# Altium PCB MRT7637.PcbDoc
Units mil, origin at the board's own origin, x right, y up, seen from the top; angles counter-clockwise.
Board outline 6000 x 4000 mil, 2 copper layers (Top Layer, Bottom Layer); 1 components, 0 nets, 5 pads, 0 vias.
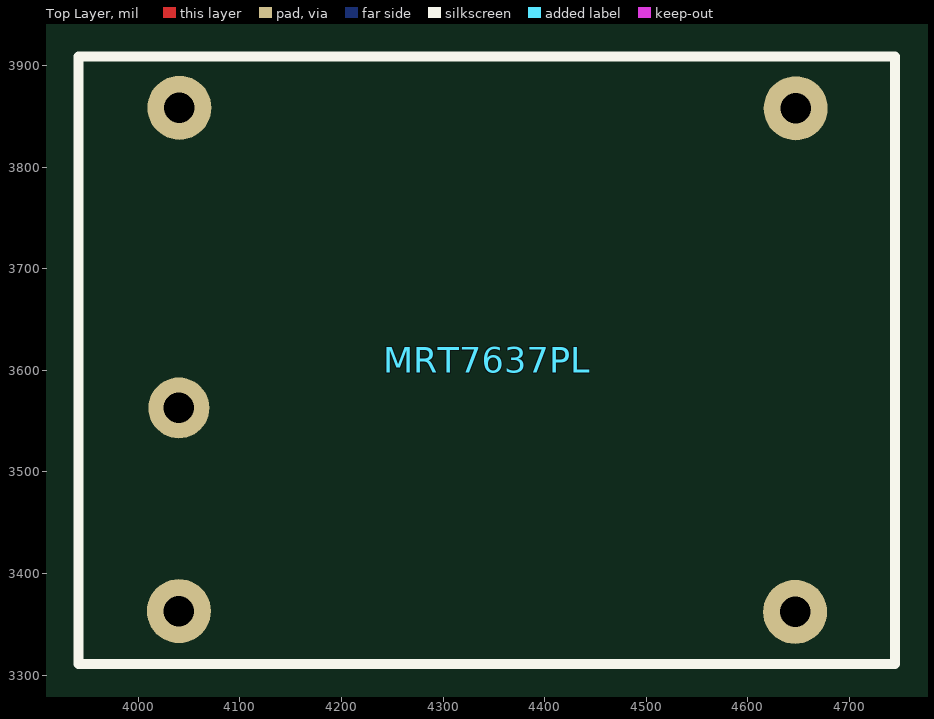
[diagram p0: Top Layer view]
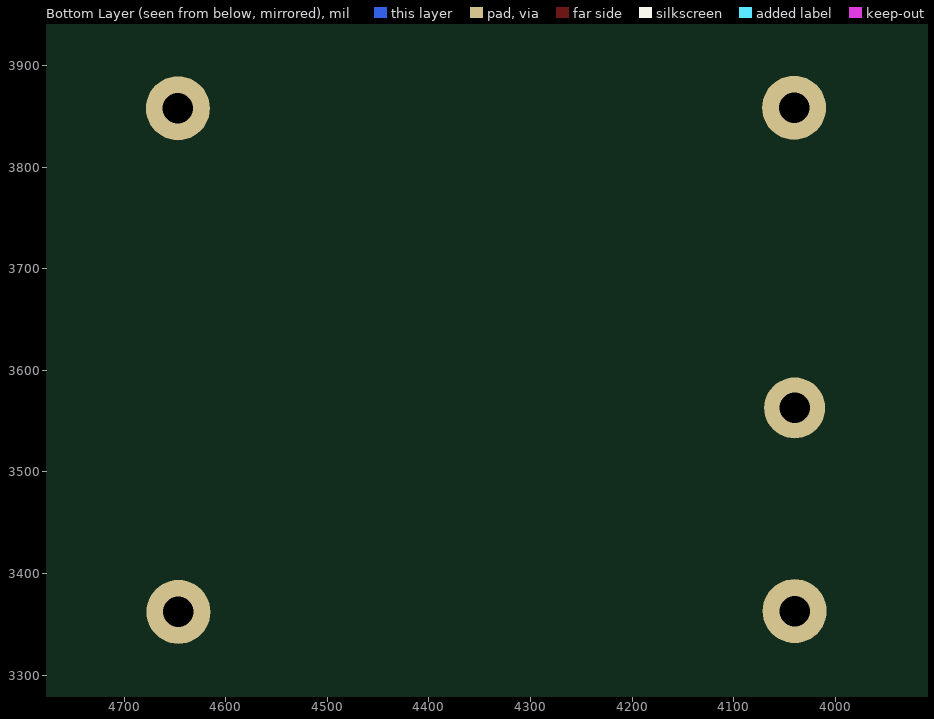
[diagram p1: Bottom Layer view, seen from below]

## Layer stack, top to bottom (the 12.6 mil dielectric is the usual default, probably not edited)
Top Solder: solder mask 0.4, Solder Resist, Dk 3.5
Top Layer: signal copper 1.4
Dielectric 1: dielectric 12.6, FR-4, Dk 4.8
Bottom Layer: signal copper 1.4
Bottom Solder: solder mask 0.4, Solder Resist, Dk 3.5

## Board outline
1000,1000 7000,1000 7000,5000 1000,5000

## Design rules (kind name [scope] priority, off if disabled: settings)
Clearance [All] p1: gap=10
PolygonConnect [All] p1: connectstyle=Relief reliefconductorwidth=10 reliefentries=4 polygonreliefangle="90 Angle" airgapwidth=10
RoutingVias [All] p1: holewidth=28 width=50 viastyle="Through Hole" minholewidth=28 minwidth=50 maxholewidth=28 maxwidth=50
SolderMaskExpansion [All] p1: expansion=4
Width [All] p1: maxlimit=10 minlimit=10 preferedwidth=10
30 further rules are at their usual default settings.

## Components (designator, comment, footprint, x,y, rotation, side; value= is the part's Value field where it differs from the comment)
MRT7637PL "Comment" MRT7637PL 4340,3605 r0 top

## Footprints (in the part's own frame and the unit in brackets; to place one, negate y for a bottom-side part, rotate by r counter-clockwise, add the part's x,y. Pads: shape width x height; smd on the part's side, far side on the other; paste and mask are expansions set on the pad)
MRT7637PL [mm]
  round 1.6 hole 0.762: 1(-7.62,-6.146) 3(-7.606,6.438) 4(7.799,6.425) 5(7.785,-6.165)
  round 1.524 hole 0.762: 2(-7.62,-1.066)
  silkscreen extent -10.13,-7.46 10.28,7.72

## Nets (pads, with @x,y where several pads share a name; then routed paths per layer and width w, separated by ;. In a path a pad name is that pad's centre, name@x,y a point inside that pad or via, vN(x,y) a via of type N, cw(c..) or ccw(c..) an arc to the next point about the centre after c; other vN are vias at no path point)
pads on no net: MRT7637PL.1 MRT7637PL.2 MRT7637PL.3 MRT7637PL.4 MRT7637PL.5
